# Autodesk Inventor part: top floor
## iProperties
Created: 2018-12
Part Number: top floor
Document SubType Name: Modeling
Designer: Harindersingh
Density: 1 g/cm^3
Author: Harindersingh
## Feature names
1. Extrusion1
